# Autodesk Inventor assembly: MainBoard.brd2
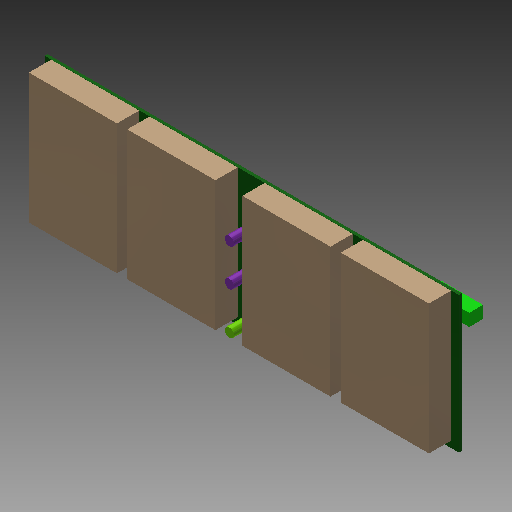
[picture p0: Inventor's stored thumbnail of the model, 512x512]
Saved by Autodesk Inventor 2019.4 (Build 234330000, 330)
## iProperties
Created: 2019-11
Part Number: MainBoard.brd2
Document SubType Name: Assembly
Designer: Willist
Author: Willist
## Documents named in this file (30)
- D:\Biblioteki\Dokumenty\,Studia\StudiaMagisterskie\Semestry\Semestr2\ProjektGupowy\GIT\Projekt-Grupowy-Minutnik\Minutnix\3d\MainBoard.brd2.iam
- D:\Biblioteki\Dokumenty\,Studia\StudiaMagisterskie\Semestry\Semestr2\ProjektGupowy\GIT\Projekt-Grupowy-Minutnik\Minutnix\3d\MainBoard.brd_Outline2.ipt
- D:\Biblioteki\Dokumenty\,Studia\StudiaMagisterskie\Semestry\Semestr2\ProjektGupowy\GIT\Projekt-Grupowy-Minutnik\Minutnix\3d\QFP80P900X900X120-32N, ATMEGA328P-AU_12.ipt
- D:\Biblioteki\Dokumenty\,Studia\StudiaMagisterskie\Semestry\Semestr2\ProjektGupowy\GIT\Projekt-Grupowy-Minutnik\Minutnix\3d\C0603, C0603_32.ipt
- D:\Biblioteki\Dokumenty\,Studia\StudiaMagisterskie\Semestry\Semestr2\ProjektGupowy\GIT\Projekt-Grupowy-Minutnik\Minutnix\3d\SMC_B, SMC_B_62.ipt
- D:\Biblioteki\Dokumenty\,Studia\StudiaMagisterskie\Semestry\Semestr2\ProjektGupowy\GIT\Projekt-Grupowy-Minutnik\Minutnix\3d\C1206, C1206_112.ipt
- D:\Biblioteki\Dokumenty\,Studia\StudiaMagisterskie\Semestry\Semestr2\ProjektGupowy\GIT\Projekt-Grupowy-Minutnik\Minutnix\3d\153CLV-0810, 153CLV-0810_222.ipt
- D:\Biblioteki\Dokumenty\,Studia\StudiaMagisterskie\Semestry\Semestr2\ProjektGupowy\GIT\Projekt-Grupowy-Minutnik\Minutnix\3d\C1210, C1210_242.ipt
- D:\Biblioteki\Dokumenty\,Studia\StudiaMagisterskie\Semestry\Semestr2\ProjektGupowy\GIT\Projekt-Grupowy-Minutnik\Minutnix\3d\CHIPLED_0603, CHIPLED_0603_262.ipt
- D:\Biblioteki\Dokumenty\,Studia\StudiaMagisterskie\Semestry\Semestr2\ProjektGupowy\GIT\Projekt-Grupowy-Minutnik\Minutnix\3d\LED5MM, LED5MM_282.ipt
- D:\Biblioteki\Dokumenty\,Studia\StudiaMagisterskie\Semestry\Semestr2\ProjektGupowy\GIT\Projekt-Grupowy-Minutnik\Minutnix\3d\SO16, PCF8574AT_312.ipt
- D:\Biblioteki\Dokumenty\,Studia\StudiaMagisterskie\Semestry\Semestr2\ProjektGupowy\GIT\Projekt-Grupowy-Minutnik\Minutnix\3d\SOT223, IC2_SOT223_332.ipt
- D:\Biblioteki\Dokumenty\,Studia\StudiaMagisterskie\Semestry\Semestr2\ProjektGupowy\GIT\Projekt-Grupowy-Minutnik\Minutnix\3d\SOP-8, TP4056_352.ipt
- D:\Biblioteki\Dokumenty\,Studia\StudiaMagisterskie\Semestry\Semestr2\ProjektGupowy\GIT\Projekt-Grupowy-Minutnik\Minutnix\3d\SSOP28, FT232RL_372.ipt
- D:\Biblioteki\Dokumenty\,Studia\StudiaMagisterskie\Semestry\Semestr2\ProjektGupowy\GIT\Projekt-Grupowy-Minutnik\Minutnix\3d\1X01, 1X01_392.ipt
- D:\Biblioteki\Dokumenty\,Studia\StudiaMagisterskie\Semestry\Semestr2\ProjektGupowy\GIT\Projekt-Grupowy-Minutnik\Minutnix\3d\9V_VOLTAGE_REGULATOR, 9V_VOLTAGE_REGULATOR_592.ipt
- D:\Biblioteki\Dokumenty\,Studia\StudiaMagisterskie\Semestry\Semestr2\ProjektGupowy\GIT\Projekt-Grupowy-Minutnik\Minutnix\3d\DR73, 10UH_612.ipt
- D:\Biblioteki\Dokumenty\,Studia\StudiaMagisterskie\Semestry\Semestr2\ProjektGupowy\GIT\Projekt-Grupowy-Minutnik\Minutnix\3d\MYTHT, LED-7-SEGM-56MM_632.ipt
- D:\Biblioteki\Dokumenty\,Studia\StudiaMagisterskie\Semestry\Semestr2\ProjektGupowy\GIT\Projekt-Grupowy-Minutnik\Minutnix\3d\SO16, TPIC6C596PW_662.ipt
- D:\Biblioteki\Dokumenty\,Studia\StudiaMagisterskie\Semestry\Semestr2\ProjektGupowy\GIT\Projekt-Grupowy-Minutnik\Minutnix\3d\VT900, VT90N1_732.ipt
- D:\Biblioteki\Dokumenty\,Studia\StudiaMagisterskie\Semestry\Semestr2\ProjektGupowy\GIT\Projekt-Grupowy-Minutnik\Minutnix\3d\SOT23, Q2_SOT23_752.ipt
- D:\Biblioteki\Dokumenty\,Studia\StudiaMagisterskie\Semestry\Semestr2\ProjektGupowy\GIT\Projekt-Grupowy-Minutnik\Minutnix\3d\CRYSTAL-SMD-2X6-CYL, 32_768KHZ_772.ipt
- D:\Biblioteki\Dokumenty\,Studia\StudiaMagisterskie\Semestry\Semestr2\ProjektGupowy\GIT\Projekt-Grupowy-Minutnik\Minutnix\3d\R0603, R0603_792.ipt
- D:\Biblioteki\Dokumenty\,Studia\StudiaMagisterskie\Semestry\Semestr2\ProjektGupowy\GIT\Projekt-Grupowy-Minutnik\Minutnix\3d\RTRIM3296Y, RTRIM3296Y_1282.ipt
- D:\Biblioteki\Dokumenty\,Studia\StudiaMagisterskie\Semestry\Semestr2\ProjektGupowy\GIT\Projekt-Grupowy-Minutnik\Minutnix\3d\F_HGP, F_HGP_1352.ipt
- D:\Biblioteki\Dokumenty\,Studia\StudiaMagisterskie\Semestry\Semestr2\ProjektGupowy\GIT\Projekt-Grupowy-Minutnik\Minutnix\3d\DO214AA, S2A_1372.ipt
- D:\Biblioteki\Dokumenty\,Studia\StudiaMagisterskie\Semestry\Semestr2\ProjektGupowy\GIT\Projekt-Grupowy-Minutnik\Minutnix\3d\MA03-2, MA03-2_1392.ipt
- D:\Biblioteki\Dokumenty\,Studia\StudiaMagisterskie\Semestry\Semestr2\ProjektGupowy\GIT\Projekt-Grupowy-Minutnik\Minutnix\3d\MINI, X2_1422.ipt
- D:\Biblioteki\Dokumenty\,Studia\StudiaMagisterskie\Semestry\Semestr2\ProjektGupowy\GIT\Projekt-Grupowy-Minutnik\Minutnix\3d\FH12-12S-0_5SH_THINER, FH12-12S-0_5S_THINNER_1452.ipt
- D:\Biblioteki\Dokumenty\,Studia\StudiaMagisterskie\Semestry\Semestr2\ProjektGupowy\GIT\Projekt-Grupowy-Minutnik\Minutnix\3d\JST-XH-03-PACKAGE-LONG-PAD, JST-XH-03-PIN-LONG-PAD_1472.ipt
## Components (122 placed, 122 different names)
1. MainBoard.brd_Outline:1
2. ATMEGA328P_2
3. C1_4
4. C2_5
5. C3_7
6. C4_8
7. C5_9
8. C6_10
9. C7_12
10. C8_13
11. C10_14
12. C14_15
13. C15_16
14. C16_17
15. C17_18
16. C18_19
17. C29_20
18. C30_21
19. C31_23
20. C32_25
21. CHRG_LED_27
22. COLON1_29
23. COLON2_30
24. EXPANDER_32
25. IC2_34
26. IC3_36
27. IC7_38
28. JP1_40
29. JP2_41
30. JP3_42
31. JP4_43
32. JP5_44
33. JP6_45
34. JP7_46
35. JP8_47
36. JP9_48
37. JP10_49
38. JP12_50
39. JP13_51
40. JP14_52
41. JP15_53
42. JP16_54
43. JP17_55
44. JP18_56
45. JP19_57
46. JP20_58
47. J_REG_9V_1_60
48. L1_62
49. LSDIGIT_MINUTES_64
50. LSDIGIT_SECONDS_65
51. LS_MIN_REG_67
52. LS_SEC_REG_68
53. MSDIGIT_MINUTES_69
54. MSDIGIT_SECONDS_70
55. MS_MIN_REG_71
56. MS_SEC_REG_72
57. PHOTORES_74
58. Q2_76
59. Q4_78
60. R1_80
61. R2_81
62. R3_82
63. R4_83
64. R5_84
65. R6_85
66. R7_86
67. R8_87
68. R9_88
69. R10_89
70. R11_90
71. R12_91
72. R13_92
73. R14_93
74. R15_94
75. R16_95
76. R17_96
77. R18_97
78. R19_98
79. R20_99
80. R21_100
81. R22_101
82. R23_102
83. R24_103
84. R25_104
85. R26_105
86. R27_106
87. R28_107
88. R29_108
89. R30_109
90. R31_110
91. R32_111
92. R33_112
93. R34_113
94. R35_114
95. R36_115
96. R39_116
97. R40_117
98. R42_118
99. R43_119
100. R44_120
101. R45_121
102. R46_122
103. R47_123
104. R48_124
105. R50_125
106. R52_126
107. R56_127
108. R57_129
109. R61_130
110. R64_131
111. R65_132
112. R66_133
113. RXLED_134
114. SG1_136
115. SHOTTKYDIODE3_138
116. SPI_JUMPERS_140
117. STDBY_LED_141
118. SWITCH_143
119. TXLED_144
120. X1_146
121. X2_148
122. X4_149
